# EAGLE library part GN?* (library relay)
ULTRA-SMALL PACKAGE SLIM POLARIZED RELAY NAiS Source: http://www.mew-europe.com/.. en_ds_61007_0000.pdf
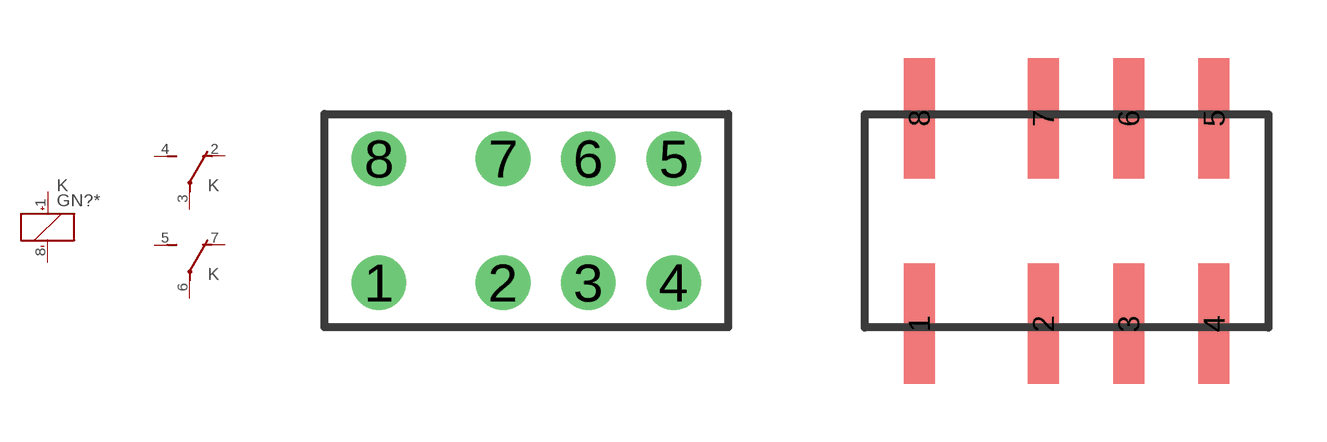
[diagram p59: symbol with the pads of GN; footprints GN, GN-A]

Designator prefix K; gates R=K+- S=U T=U

## GN2001H (MF: AROMAT/ MATSUSHITA; MPN: AGN2001H; OC_FARNELL: unknown; OC_NEWARK: 10C3281), GN20003 (MPN: AGN20003; OC_FARNELL: unknown; OC_NEWARK: 13P0830), GN2004H (MPN: AGN2004H; OC_FARNELL: 3104771; OC_NEWARK: 13P0834), GN20006 (MPN: AGN20006; OC_FARNELL: unknown; OC_NEWARK: 13P0831), GN20009 (MF: AROMAT/ MATSUSHITA; MPN: AGN20009; OC_FARNELL: unknown; OC_NEWARK: 10C3280), GN20012 (MPN: AGN20012; OC_FARNELL: 3104783; OC_NEWARK: 13P0832), GN20024 (MPN: AGN20024; OC_FARNELL: 4364211; OC_NEWARK: 13P0833)  [GN]
1  R:+  pas
2  S:O  pas
3  S:P  pas
4  S:S  pas
5  T:S  pas
6  T:P  pas
7  T:O  pas
8  R:-  pas

## GN2101H (OC_FARNELL: unknown; OC_NEWARK: unknown), GN21003 (MPN: AGN21003; OC_FARNELL: unknown; OC_NEWARK: 15P8576), GN2104H (MPN: AGN2104H; OC_FARNELL: unknown; OC_NEWARK: 15P8579), GN21006 (MPN: AGN21006; OC_FARNELL: unknown; OC_NEWARK: 15P8577), GN21009 (OC_FARNELL: unknown; OC_NEWARK: unknown), GN21012 (MPN: AGN21012; OC_FARNELL: unknown; OC_NEWARK: 15P8578), GN21024 (OC_FARNELL: unknown; OC_NEWARK: unknown)  [GN]
1  R:-  pas
2  S:O  pas
3  S:P  pas
4  S:S  pas
5  T:S  pas
6  T:P  pas
7  T:O  pas
8  R:+  pas

## GN200A1H (OC_FARNELL: unknown; OC_NEWARK: unknown), GN200A03 (MPN: AGN200A03; OC_FARNELL: unknown; OC_NEWARK: 13P0812), GN200A4H (MPN: AGN200A4H; OC_FARNELL: 3104795; OC_NEWARK: 13P0820), GN200A06 (MPN: AGN200A06; OC_FARNELL: unknown; OC_NEWARK: 13P0814), GN200A09 (MPN: AGN200A09Z; OC_FARNELL: unknown; OC_NEWARK: 13P0815), GN200A12 (MPN: AGN200A12; OC_FARNELL: 3104801; OC_NEWARK: 13P0816), GN200A24 (MPN: AGN200A24; OC_FARNELL: unknown; OC_NEWARK: 13P0818)  [GN-A]
Pads as for GN

## GN200S1H, GN200S03 (MPN: AGN200S03; OC_FARNELL: unknown; OC_NEWARK: 13P0822), GN200S4H (MPN: AGN200S4H; OC_FARNELL: unknown; OC_NEWARK: 13P0828), GN200S06 (OC_FARNELL: unknown; OC_NEWARK: unknown), GN200S09 (OC_FARNELL: unknown; OC_NEWARK: unknown), GN200S12 (MPN: AGN200S12; OC_FARNELL: 1448335; OC_NEWARK: 13P0824), GN200S24 (MPN: AGN200S24; OC_FARNELL: unknown; OC_NEWARK: 13P0826)  [GN-S]
Pads as for GN

## GN210A1H (OC_FARNELL: unknown; OC_NEWARK: unknown), GN210A03 (MPN: AGN210A03; OC_FARNELL: unknown; OC_NEWARK: 15P8571), GN210A4H (MPN: AGN210A4H; OC_FARNELL: unknown; OC_NEWARK: 15P8573), GN210A06 (OC_FARNELL: unknown; OC_NEWARK: unknown), GN210A09 (OC_FARNELL: unknown; OC_NEWARK: unknown), GN210A12 (MF: AROMAT/ MATSUSHITA; MPN: AGN210A12; OC_FARNELL: unknown; OC_NEWARK: 10C3303), GN210A24 (OC_FARNELL: unknown; OC_NEWARK: unknown)  [GN-A]
Pads as for GN

## GN210S1H (OC_FARNELL: unknown; OC_NEWARK: unknown), GN210S03 (MPN: AGN210S03; OC_FARNELL: unknown; OC_NEWARK: 15P8575), GN210S4H (OC_FARNELL: unknown; OC_NEWARK: unknown), GN210S06 (OC_FARNELL: unknown; OC_NEWARK: unknown), GN210S09 (OC_FARNELL: unknown; OC_NEWARK: unknown), GN210S12 (MF: AROMAT/ MATSUSHITA; MPN: AGN210S12; OC_FARNELL: unknown; OC_NEWARK: 10C3320), GN210S24 (OC_FARNELL: unknown; OC_NEWARK: unknown)  [GN-S]
Pads as for GN

## Footprint GN (pad centres in mm)
ULTRA-SMALL PACKAGE SLIM POLARIZED RELAY NAiS Source: http://www.mew-europe.com/.. en_ds_61007_0000.pdf
drill 0.9 round: 1 -3.835,-1.6; 2 -0.635,-1.6; 3 1.565,-1.6; 4 3.765,-1.6; 5 3.765,1.6; 6 1.565,1.6; 7 -0.635,1.6; 8 -3.835,1.6

## Footprint GN-A (pad centres in mm)
ULTRA-SMALL PACKAGE SLIM POLARIZED RELAY NAiS Source: http://www.mew-europe.com/.. en_ds_61007_0000.pdf
smd 0.8 x 3.1: 1 -3.835,-2.65; 2 -0.635,-2.65; 3 1.565,-2.65; 4 3.765,-2.65; 5 3.765,2.65; 6 1.565,2.65; 7 -0.635,2.65; 8 -3.835,2.65

## Footprint GN-S (pad centres in mm)
ULTRA-SMALL PACKAGE SLIM POLARIZED RELAY NAiS Source: http://www.mew-europe.com/.. en_ds_61007_0000.pdf
smd 0.8 x 2.25: 1 -3.835,-2.225; 2 -0.635,-2.225; 3 1.565,-2.225; 4 3.765,-2.225; 5 3.765,2.225; 6 1.565,2.225; 7 -0.635,2.225; 8 -3.835,2.225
